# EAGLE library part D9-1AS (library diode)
8 DIODES SIL, common anode (single gate)
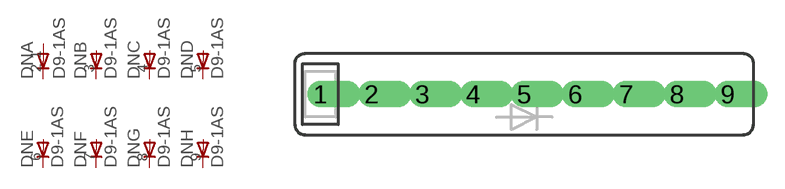
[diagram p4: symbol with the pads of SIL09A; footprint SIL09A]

Designator prefix DN; gates A=DN1 B=DNA C=DNA D=DNA E=DNA F=DNA G=DNA H=DNA

## D9-1AS  [SIL09A]
1  A:A  pas
2  A:C  pas
3  B:C  pas
4  C:C  pas
5  D:C  pas
6  E:C  pas
7  F:C  pas
8  G:C  pas
9  H:C  pas

## Footprint SIL09A (pad centres in mm)
8 DIODES single in line 8 diodes with common anode
drill 0.813 offset: 1 -10.16,0; 2 -7.62,0; 3 -5.08,0; 4 -2.54,0; 5 0,0; 6 2.54,0; 7 5.08,0; 8 7.62,0; 9 10.16,0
